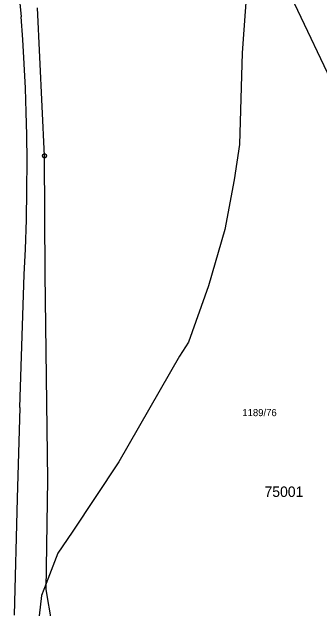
# Model space of a CAD drawing. Extents: x -789470 to -786707, y -1118640 to -1114455.
# Drawn here: x -787703.3 to -787629.8, y -1116651.3 to -1116508.7 of the extents above; entities that cross this region are included whole.
import ezdxf

# ---------------------------------------------------------------- set-up
doc = ezdxf.new("R2010")
doc.units = 0
for name, color, linetype in [('1', 7, 'Continuous'), ('11', 7, 'Continuous'), ('2', 7, 'Continuous'), ('6', 7, 'Continuous'), ('8', 7, 'Continuous')]:
    doc.layers.add(name, color=color, linetype=linetype)

msp = doc.modelspace()

# ---------------------------------------------------------------- linework, layer by layer
at = {"layer": '1'}
for p, q in [((-787635.8, -1116506.59), (-787568.9, -1116647.88)), ((-787695.53, -1116543.16), (-787697.17, -1116507.73)), ((-787695.36, -1116571.42), (-787695.53, -1116543.16)), ((-787694.77, -1116620.61), (-787695.36, -1116571.42)), ((-787695.13, -1116646.88), (-787694.77, -1116620.61)), ((-787693.44, -1116656.57), (-787695.13, -1116646.88))]:
    msp.add_line(p, q, dxfattribs=at)
at = {"layer": '11'}
msp.add_lwpolyline([(-787682.47, -1116330.41), (-787682.5, -1116331.13), (-787683.51, -1116357.47), (-787678.19, -1116382.89), (-787670.29, -1116401.57), (-787663.71, -1116428.69), (-787655.44, -1116455.83), (-787649.65, -1116474.49), (-787647.6, -1116484.65), (-787646.4, -1116493.12), (-787648.27, -1116518.48), (-787648.86, -1116540.46), (-787650.19, -1116548.91), (-787652.39, -1116560.73), (-787656.3, -1116574.23), (-787661.06, -1116587.72), (-787663.2, -1116591.08), (-787677.78, -1116616.32), (-787688.91, -1116633.13), (-787692.34, -1116638.18), (-787695.11, -1116645.4), (-787696.22, -1116648.29), (-787697.58, -1116660.12)], dxfattribs=at)
at = {"layer": '6'}
for p, q in [((-787701.42, -1116603.36), (-787700.4, -1116571.55)), ((-787701.42, -1116603.36), (-787702.06, -1116625.08)), ((-787702.06, -1116625.08), (-787702.77, -1116653))]:
    msp.add_line(p, q, dxfattribs=at)
for points in [[(-787708.76, -1116471.47), (-787707.66, -1116475.3), (-787706.5, -1116479.65), (-787705.44, -1116484.02), (-787704.47, -1116488.41), (-787703.69, -1116492.32), (-787702.95, -1116496.37), (-787702.2, -1116501.07), (-787701.55, -1116505.78), (-787701.08, -1116509.87)], [(-787700.4, -1116571.55), (-787700.11, -1116565.45), (-787699.87, -1116558.41), (-787699.74, -1116551.37), (-787699.71, -1116544.33), (-787699.78, -1116538.22), (-787699.9, -1116532.73), (-787700.09, -1116526.93), (-787700.36, -1116521.14), (-787700.69, -1116515.35), (-787701.08, -1116509.87)]]:
    msp.add_lwpolyline(points, dxfattribs=at)
at = {"layer": '8'}
msp.add_line((-787695.65, -1116543.16), (-787695.41, -1116543.16), dxfattribs=at)
msp.add_lwpolyline([(-787695.38, -1116542.68), (-787695.13, -1116542.86), (-787695.03, -1116543.15), (-787695.13, -1116543.44), (-787695.38, -1116543.62), (-787695.69, -1116543.62), (-787695.94, -1116543.44), (-787696.04, -1116543.15), (-787695.94, -1116542.86), (-787695.69, -1116542.68)], close=True, dxfattribs=at)

# ---------------------------------------------------------------- texts
at = {"layer": '11'}
msp.add_text('75001', height=2.5, dxfattribs=at).set_placement((-787642.9, -1116624.73))
at = {"layer": '2'}
msp.add_text('1189/76', height=1.7, dxfattribs=at).set_placement((-787648.2, -1116605.41))

doc.saveas('drawing.dxf')
